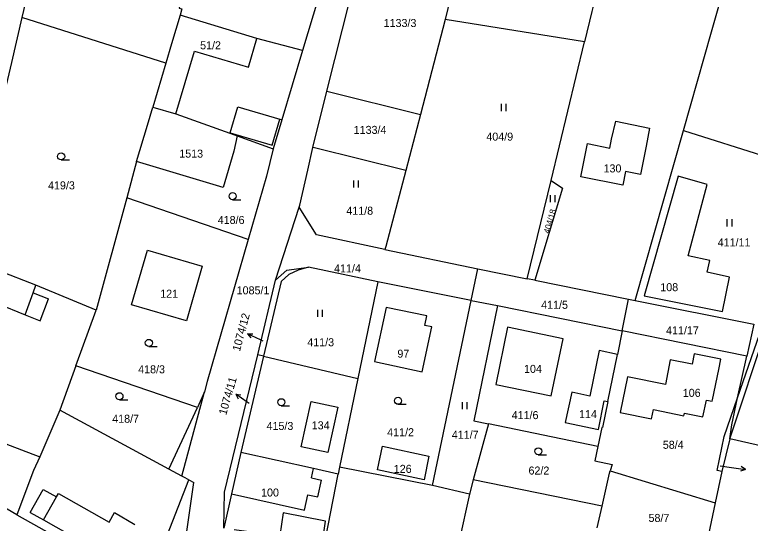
# Model space of a CAD drawing. Extents: x -746176 to -739709, y -1128407 to -1124482.
# Drawn here: x -742393.3 to -742237.2, y -1125968.5 to -1125860.6 of the extents above; entities that cross this region are included whole.
import ezdxf

# ---------------------------------------------------------------- set-up
doc = ezdxf.new("R2010")
doc.units = 0
for name, color, linetype in [('Hranice parcel', 7, 'Continuous'), ('Parcelní čísla', 7, 'Continuous'), ('Pop  PČ popisy', 7, 'Continuous'), ('Vnitřní kresba', 7, 'Continuous'), ('Značky kultur', 7, 'Continuous')]:
    doc.layers.add(name, color=color, linetype=linetype)

msp = doc.modelspace()

# ---------------------------------------------------------------- linework, layer by layer
at = {"layer": 'Hranice parcel'}
for p, q in [((-742386.83, -1125839.6), (-742391.8, -1125861.15)), ((-742297.47, -1125842.97), (-742301.95, -1125861.59)), ((-742326.59, -1125849.41), (-742332.22, -1125868.16)), ((-742327.06, -1125876.83), (-742320.67, -1125851.28)), ((-742361.26, -1125870.87), (-742391.8, -1125861.15)), ((-742301.95, -1125861.59), (-742307.2, -1125881.77)), ((-742272.35, -1125866.33), (-742301.95, -1125861.59)), ((-742279.49, -1125895.76), (-742272.35, -1125866.33)), ((-742361.26, -1125870.87), (-742364, -1125880.2)), ((-742330.04, -1125888.75), (-742327.06, -1125876.83)), ((-742327.06, -1125876.83), (-742307.2, -1125881.77)), ((-742307.2, -1125881.77), (-742310.3, -1125893.66)), ((-742265.76, -1125883.17), (-742258.57, -1125884.66)), ((-742346.08, -1125886.31), (-742338.49, -1125889.03)), ((-742261.6, -1125921.22), (-742251.35, -1125885.17)), ((-742251.35, -1125885.17), (-742230.88, -1125891.65)), ((-742367.46, -1125891.72), (-742369.56, -1125899.45)), ((-742284.56, -1125916.62), (-742279.49, -1125895.76)), ((-742369.56, -1125899.45), (-742376.04, -1125923.32)), ((-742343.77, -1125908.28), (-742369.56, -1125899.45)), ((-742337.98, -1125916.93), (-742332.93, -1125901.45)), ((-742314.74, -1125910.42), (-742295.02, -1125914.52)), ((-742316.28, -1125917.27), (-742330.95, -1125914.18)), ((-742296.43, -1125921.26), (-742295.02, -1125914.52)), ((-742295.02, -1125914.52), (-742284.56, -1125916.62)), ((-742341.73, -1125932.77), (-742337.98, -1125916.93)), ((-742316.28, -1125917.27), (-742320.52, -1125937.81)), ((-742296.43, -1125921.26), (-742316.28, -1125917.27)), ((-742282.91, -1125916.95), (-742284.56, -1125916.62)), ((-742282.91, -1125916.95), (-742263.01, -1125920.94)), ((-742264.39, -1125927.72), (-742263.01, -1125920.94)), ((-742263.01, -1125920.94), (-742261.6, -1125921.22)), ((-742304.63, -1125960.54), (-742296.43, -1125921.26)), ((-742296.43, -1125921.26), (-742290.84, -1125922.32)), ((-742290.84, -1125922.32), (-742264.39, -1125927.72)), ((-742380.33, -1125935.12), (-742376.04, -1125923.32)), ((-742264.39, -1125927.72), (-742265.4, -1125932.68)), ((-742237.93, -1125933.1), (-742264.39, -1125927.72)), ((-742392.86, -1125966.72), (-742452.23, -1125932.44)), ((-742340.51, -1125933.06), (-742345.34, -1125953.5)), ((-742340.51, -1125933.06), (-742341.73, -1125932.77)), ((-742340.51, -1125933.06), (-742320.52, -1125937.81)), ((-742267.46, -1125942.71), (-742265.4, -1125932.68)), ((-742239.87, -1125941.89), (-742237.93, -1125933.1)), ((-742380.33, -1125935.12), (-742383.73, -1125944.51)), ((-742354.55, -1125943.93), (-742380.33, -1125935.12)), ((-742320.52, -1125937.81), (-742324.4, -1125956.6)), ((-742353.05, -1125940.67), (-742354.55, -1125943.93)), ((-742360.59, -1125957.08), (-742354.55, -1125943.93)), ((-742383.73, -1125944.51), (-742387.99, -1125954.45)), ((-742360.59, -1125957.08), (-742383.73, -1125944.51)), ((-742292.77, -1125947.44), (-742295.99, -1125959.35)), ((-742269.58, -1125952.24), (-742292.77, -1125947.44)), ((-742241.51, -1125950.63), (-742243.24, -1125957.53)), ((-742215.07, -1125956.62), (-742241.51, -1125950.63)), ((-742324.4, -1125956.6), (-742324.69, -1125958.1)), ((-742304.63, -1125960.54), (-742324.4, -1125956.6)), ((-742266.93, -1125957.38), (-742244.64, -1125964.23)), ((-742243.24, -1125957.53), (-742244.64, -1125964.23)), ((-742243.24, -1125957.53), (-742244.22, -1125957.34)), ((-742295.99, -1125959.35), (-742296.81, -1125962.38)), ((-742268.65, -1125964.88), (-742295.99, -1125959.35)), ((-742296.81, -1125962.38), (-742304.63, -1125960.54)), ((-742296.81, -1125962.38), (-742300.78, -1125980.44)), ((-742244.64, -1125964.23), (-742246.75, -1125974.33))]:
    msp.add_line(p, q, dxfattribs=at)
for points in [[(-742257.65, -1125810.78), (-742268.09, -1125852.98), (-742269.07, -1125852.77), (-742269.89, -1125856.16), (-742270.81, -1125859.92), (-742272.35, -1125866.33)], [(-742251.35, -1125885.17), (-742245.39, -1125864.19), (-742231.78, -1125816.3)], [(-742353.96, -1125840.78), (-742358.42, -1125859.19), (-742357.84, -1125859.34), (-742358.23, -1125860.65)], [(-742391.8, -1125861.15), (-742394.01, -1125870.7), (-742398.15, -1125887.84), (-742401.44, -1125899.49)], [(-742358.23, -1125860.65), (-742360.05, -1125866.75), (-742361.26, -1125870.87)], [(-742332.22, -1125868.16), (-742341.91, -1125865.6), (-742358.23, -1125860.65)], [(-742332.22, -1125868.16), (-742336.64, -1125882.89), (-742338.49, -1125889.03)], [(-742241.51, -1125950.63), (-742233.66, -1125926.96), (-742223.23, -1125894.07), (-742218.91, -1125880.44), (-742217.69, -1125875.07), (-742216.33, -1125869.06)], [(-742367.46, -1125891.72), (-742365.16, -1125884), (-742364, -1125880.2)], [(-742364, -1125880.2), (-742359.13, -1125881.64), (-742347.65, -1125885.75), (-742346.08, -1125886.31)], [(-742258.57, -1125884.66), (-742259.27, -1125888.5), (-742260.46, -1125894.48), (-742263.65, -1125893.85), (-742264.23, -1125896.78), (-742273.15, -1125895.02), (-742271.72, -1125887.95), (-742267.02, -1125888.9), (-742266.64, -1125887), (-742265.76, -1125883.17)], [(-742346.08, -1125886.31), (-742346.82, -1125889.56), (-742349.06, -1125897.29), (-742367.46, -1125891.72)], [(-742338.49, -1125889.03), (-742339.9, -1125894.84), (-742343.77, -1125908.28)], [(-742332.93, -1125901.45), (-742332.83, -1125901.02), (-742331.14, -1125893.58), (-742330.04, -1125888.75)], [(-742310.3, -1125893.66), (-742329.73, -1125888.83), (-742330.04, -1125888.75)], [(-742310.3, -1125893.66), (-742314.57, -1125909.78), (-742314.74, -1125910.42)], [(-742239.87, -1125941.89), (-742234.61, -1125926.63), (-742224.19, -1125893.77)], [(-742279.49, -1125895.76), (-742277.04, -1125897.38), (-742282.91, -1125916.95)], [(-742252.47, -1125894.85), (-742259.69, -1125920.29), (-742243.08, -1125923.55), (-742241.58, -1125916.3), (-742246.33, -1125915.23), (-742245.79, -1125912.79), (-742250.41, -1125911.75), (-742246.32, -1125896.62), (-742252.47, -1125894.85)], [(-742314.74, -1125910.42), (-742329.26, -1125907.3), (-742332.93, -1125901.45)], [(-742343.77, -1125908.28), (-742352.46, -1125938.44), (-742353.05, -1125940.67)], [(-742356.87, -1125925.57), (-742368.52, -1125922.14), (-742365.15, -1125910.57), (-742353.51, -1125913.99), (-742356.87, -1125925.57)], [(-742376.04, -1125923.32), (-742388.87, -1125917.99), (-742404.91, -1125911.78)], [(-742330.95, -1125914.18), (-742333.17, -1125914.81), (-742335.12, -1125915.74), (-742336.77, -1125917.22), (-742340.51, -1125933.06)], [(-742337.98, -1125916.93), (-742335.56, -1125914.84), (-742330.95, -1125914.18)], [(-742290.84, -1125922.32), (-742295.85, -1125946.81), (-742292.77, -1125947.44)], [(-742261.6, -1125921.22), (-742236.44, -1125926.26), (-742237.93, -1125933.1)], [(-742305.85, -1125924.52), (-742314.47, -1125922.77), (-742316.95, -1125934.19), (-742306.85, -1125936.36), (-742304.8, -1125926.85), (-742306.27, -1125926.55), (-742305.85, -1125924.52)], [(-742288.73, -1125926.94), (-742291.23, -1125939.08), (-742279.43, -1125941.49), (-742276.92, -1125929.36), (-742288.73, -1125926.94)], [(-742265.4, -1125932.68), (-742269.24, -1125931.85), (-742271.28, -1125941.54), (-742275.1, -1125940.73), (-742276.46, -1125947.18), (-742269.43, -1125948.6), (-742268.18, -1125942.58), (-742267.46, -1125942.71)], [(-742348.95, -1125969.57), (-742348.77, -1125961.93), (-742341.73, -1125932.77)], [(-742249.09, -1125932.57), (-742249.52, -1125934.75), (-742254.17, -1125933.84), (-742255.18, -1125939.05), (-742263.28, -1125937.42), (-742264.8, -1125945), (-742258.18, -1125946.38), (-742257.75, -1125944.36), (-742251.29, -1125945.7), (-742251.18, -1125945.16), (-742247.23, -1125945.98), (-742246.48, -1125942.4), (-742245.29, -1125942.65), (-742245.23, -1125942.35), (-742243.85, -1125935.89), (-742243.41, -1125933.71), (-742249.09, -1125932.57)], [(-742324.73, -1125943.91), (-742326.85, -1125953.53), (-742332.56, -1125952.31), (-742330.42, -1125942.66), (-742324.73, -1125943.91)], [(-742267.46, -1125942.71), (-742268.58, -1125948.23), (-742268.73, -1125948.2), (-742269.58, -1125952.24)], [(-742244.22, -1125957.34), (-742242.72, -1125950.14), (-742239.87, -1125941.89)], [(-742241.51, -1125950.63), (-742241.14, -1125947.64), (-742239.87, -1125941.89)], [(-742417.31, -1125943.6), (-742412.38, -1125945.19), (-742387.99, -1125954.45)], [(-742315.28, -1125952.17), (-742305.42, -1125954.28), (-742306.43, -1125959.32), (-742316.33, -1125957.18), (-742315.28, -1125952.17)], [(-742345.34, -1125953.5), (-742347.31, -1125962.26), (-742348.95, -1125969.57)], [(-742324.69, -1125958.1), (-742329.9, -1125956.94), (-742345.34, -1125953.5)], [(-742269.58, -1125952.24), (-742270.22, -1125955.3), (-742266.54, -1125956.05), (-742266.93, -1125957.38)], [(-742387.99, -1125954.45), (-742389.36, -1125957.36), (-742392.86, -1125966.72)], [(-742357.41, -1125958.73), (-742357.86, -1125958.57), (-742360.59, -1125957.08)], [(-742327.47, -1125972.62), (-742326.77, -1125969.01), (-742324.69, -1125958.1)], [(-742268.65, -1125964.88), (-742267.07, -1125957.87), (-742266.93, -1125957.38)], [(-742365.43, -1125982.55), (-742356.37, -1125959.31), (-742357.41, -1125958.73)], [(-742269.67, -1125969.51), (-742269.48, -1125968.58), (-742268.65, -1125964.88)], [(-742392.86, -1125966.72), (-742375.94, -1125976.23), (-742374.7, -1125977.14), (-742365.43, -1125982.55)], [(-742327.47, -1125972.62), (-742328.01, -1125972.53), (-742327.37, -1125968.09), (-742336.35, -1125966.33), (-742337.09, -1125971.11), (-742340.95, -1125970.71), (-742346.78, -1125969.9)]]:
    msp.add_lwpolyline(points, dxfattribs=at)
at = {"layer": 'Pop  PČ popisy'}
for p, q in [((-742343.89, -1125928.33), (-742342.77, -1125928.3)), ((-742341.17, -1125929.6), (-742343.89, -1125928.33)), ((-742343.89, -1125928.33), (-742343.19, -1125929.21)), ((-742340.63, -1125929.86), (-742341.17, -1125929.6)), ((-742343.96, -1125942.86), (-742346.42, -1125941.14)), ((-742346.42, -1125941.14), (-742345.31, -1125941.3)), ((-742346.42, -1125941.14), (-742345.89, -1125942.12)), ((-742343.6, -1125943.11), (-742343.96, -1125942.86)), ((-742243.59, -1125956.38), (-742241.17, -1125956.7)), ((-742241.17, -1125956.7), (-742238.2, -1125957.12)), ((-742238.2, -1125957.12), (-742239.12, -1125956.48)), ((-742238.2, -1125957.12), (-742239.26, -1125957.47))]:
    msp.add_line(p, q, dxfattribs=at)
at = {"layer": 'Vnitřní kresba'}
for p, q in [((-742343.69, -1125871.72), (-742341.91, -1125865.6)), ((-742359.13, -1125881.64), (-742355.15, -1125868.33)), ((-742355.15, -1125868.33), (-742343.69, -1125871.72)), ((-742347.62, -1125885.65), (-742346, -1125880.14)), ((-742346, -1125880.14), (-742337.04, -1125882.77)), ((-742338.65, -1125888.24), (-742337.04, -1125882.77)), ((-742337.04, -1125882.77), (-742336.64, -1125882.89)), ((-742347.65, -1125885.75), (-742347.62, -1125885.65)), ((-742347.62, -1125885.65), (-742338.65, -1125888.24)), ((-742389.45, -1125919.59), (-742388.87, -1125917.99)), ((-742402.22, -1125919.77), (-742391.15, -1125924.26)), ((-742391.15, -1125924.26), (-742389.45, -1125919.59)), ((-742389.45, -1125919.59), (-742386.16, -1125920.91)), ((-742387.95, -1125925.55), (-742386.16, -1125920.91)), ((-742391.15, -1125924.26), (-742387.95, -1125925.55)), ((-742357.86, -1125958.57), (-742353.05, -1125940.67)), ((-742330.33, -1125958.91), (-742329.9, -1125956.94)), ((-742357.49, -1125975.36), (-742355.32, -1125959.9)), ((-742356.37, -1125959.31), (-742355.32, -1125959.9)), ((-742330.33, -1125958.91), (-742328.18, -1125959.38)), ((-742328.97, -1125962.95), (-742328.18, -1125959.38)), ((-742390.09, -1125966.29), (-742387.32, -1125961.4)), ((-742387.32, -1125961.4), (-742384.45, -1125962.91)), ((-742387.23, -1125967.82), (-742384.45, -1125962.91)), ((-742384.45, -1125962.91), (-742384.05, -1125962.22)), ((-742384.05, -1125962.22), (-742373.29, -1125968.32)), ((-742347.31, -1125962.26), (-742331.83, -1125965.77)), ((-742331.83, -1125965.77), (-742331.11, -1125962.48)), ((-742331.11, -1125962.48), (-742328.97, -1125962.95)), ((-742390.09, -1125966.29), (-742387.23, -1125967.82)), ((-742373.29, -1125968.32), (-742372.12, -1125966.26)), ((-742372.12, -1125966.26), (-742367.86, -1125968.77)), ((-742387.23, -1125967.82), (-742366.83, -1125979.29))]:
    msp.add_line(p, q, dxfattribs=at)
at = {"layer": 'Značky kultur'}
for p, q in [((-742290.02, -1125881.03), (-742290.02, -1125879.53)), ((-742289.02, -1125881.03), (-742289.02, -1125879.53)), ((-742383.48, -1125891.41), (-742381.73, -1125891.41)), ((-742321.38, -1125897.26), (-742321.38, -1125895.76)), ((-742320.38, -1125897.26), (-742320.38, -1125895.76)), ((-742279.62, -1125900.39), (-742279.62, -1125898.89)), ((-742278.62, -1125900.39), (-742278.62, -1125898.89)), ((-742347.08, -1125899.85), (-742345.33, -1125899.85)), ((-742242.07, -1125905.51), (-742242.07, -1125904.01)), ((-742241.07, -1125905.51), (-742241.07, -1125904.01)), ((-742328.97, -1125924.71), (-742328.97, -1125923.21)), ((-742327.97, -1125924.71), (-742327.97, -1125923.21)), ((-742364.86, -1125931), (-742363.11, -1125931)), ((-742371.1, -1125942.32), (-742369.35, -1125942.32)), ((-742336.74, -1125943.59), (-742334.99, -1125943.59)), ((-742311.96, -1125943.29), (-742310.21, -1125943.29)), ((-742298.29, -1125944.34), (-742298.29, -1125942.84)), ((-742297.29, -1125944.34), (-742297.29, -1125942.84)), ((-742282.19, -1125954.01), (-742280.44, -1125954.01))]:
    msp.add_line(p, q, dxfattribs=at)
for centre in [(-742383.48, -1125890.66), (-742347.08, -1125899.1), (-742364.86, -1125930.25), (-742371.1, -1125941.57), (-742336.74, -1125942.84), (-742311.96, -1125942.54), (-742282.19, -1125953.26)]:
    msp.add_circle(centre, 0.75, dxfattribs=at)

# ---------------------------------------------------------------- texts
at = {"layer": 'Parcelní čísla'}
for s, p in [('1133/3', (-742315.02, -1125863.19)), ('51/2', (-742353.98, -1125867.92)), ('1133/4', (-742321.38, -1125885.88)), ('404/9', (-742293.22, -1125887.31)), ('1513', (-742358.41, -1125890.92)), ('130', (-742268.34, -1125894.06)), ('419/3', (-742386.26, -1125897.66)), ('411/8', (-742322.94, -1125903.04)), ('418/6', (-742350.24, -1125905)), ('411/11', (-742244.11, -1125909.76)), ('411/4', (-742325.54, -1125915.28)), ('108', (-742256.29, -1125919.27)), ('121', (-742362.45, -1125920.66)), ('1085/1', (-742346.22, -1125919.94)), ('411/5', (-742281.58, -1125923.01)), ('411/17', (-742255.06, -1125928.43)), ('411/3', (-742331.23, -1125930.96)), ('97', (-742312.1, -1125933.39)), ('418/3', (-742367.13, -1125936.7)), ('104', (-742285.22, -1125936.61)), ('106', (-742251.52, -1125941.7)), ('418/7', (-742372.64, -1125947.2)), ('411/6', (-742287.84, -1125946.43)), ('114', (-742273.54, -1125946.22)), ('415/3', (-742339.88, -1125948.73)), ('134', (-742330.29, -1125948.6)), ('411/2', (-742314.27, -1125950.06)), ('411/7', (-742300.55, -1125950.59)), ('58/4', (-742255.76, -1125952.73)), ('126', (-742312.87, -1125957.84)), ('62/2', (-742284.27, -1125958.2)), ('100', (-742341.04, -1125962.86)), ('58/7', (-742258.79, -1125968.26))]:
    msp.add_text(s, height=1.7, dxfattribs=at).set_placement(p)
for s, height, rotation, p in [('404/18', 1.288, 74, (-742279.85, -1125907.15)), ('1074/12', 1.7, 75, (-742345.53, -1125932.15)), ('1074/11', 1.7, 74, (-742348.44, -1125945.68))]:
    msp.add_text(s, height=height, rotation=rotation, dxfattribs=at).set_placement(p)

doc.saveas('drawing.dxf')
